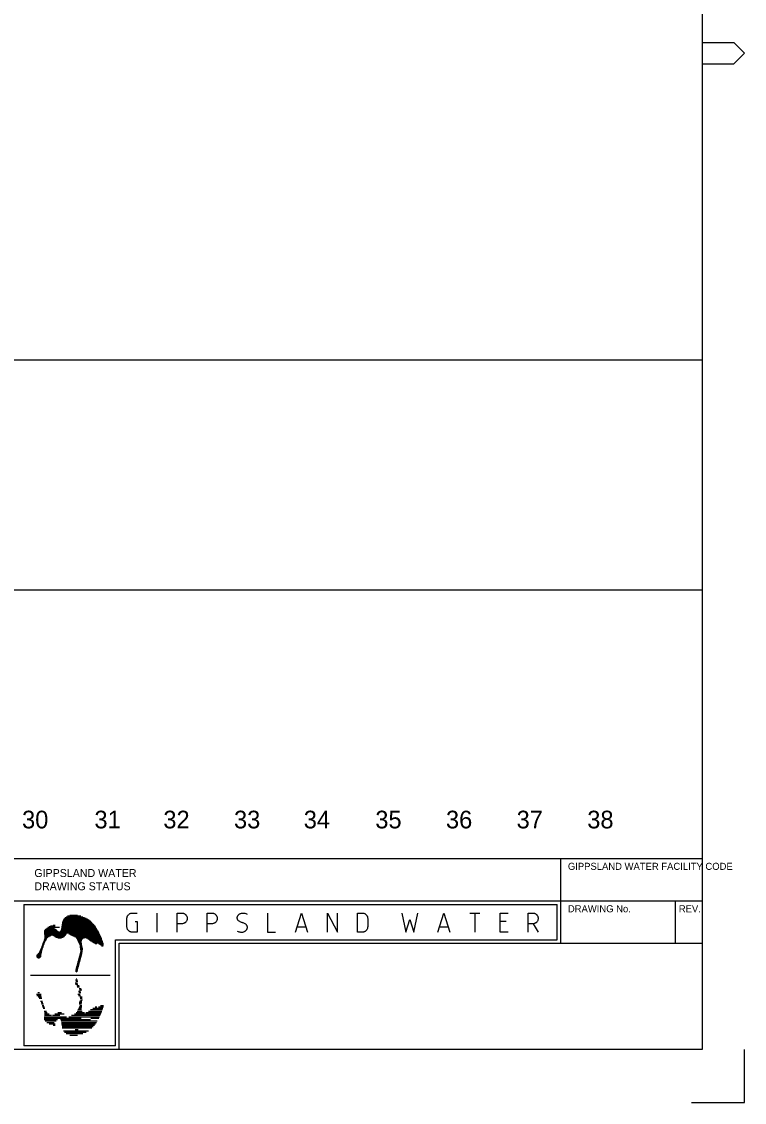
# Model space of a CAD drawing. Extents: x 0 to 841, y 0 to 594.
# Drawn here: x 636.4 to 841, y 0 to 305.7 of the extents above; entities that cross this region are included whole.
import ezdxf

# ---------------------------------------------------------------- set-up
doc = ezdxf.new("R2010")
doc.units = 0
doc.layers.add('A1BORDER', color=7, linetype='Continuous')
doc.layers.add('Level 1', color=7, linetype='Continuous')

msp = doc.modelspace()

# ---------------------------------------------------------------- linework, layer by layer
at = {"layer": 'A1BORDER'}
for p, q in [((829, 581), (829, 15)), ((829, 299.76), (838, 299.76)), ((838, 299.76), (841, 296.76)), ((838, 293.76), (841, 296.76)), ((829, 293.76), (838, 293.76)), ((592.5, 69), (829, 69)), ((789, 45), (789, 69)), ((28, 57), (829, 57)), ((637, 56), (788, 56)), ((637, 56), (637, 16)), ((788, 46), (788, 56)), ((821.5, 45), (821.5, 57)), ((648.53, 52.12), (654.64, 52.12)), ((648.74, 52.32), (654.24, 52.32)), ((649.02, 52.52), (653.76, 52.52)), ((649.39, 52.72), (653.15, 52.72)), ((650.01, 52.92), (652.2, 52.92)), ((643.04, 48.92), (646.16, 48.92)), ((643.26, 49.12), (645.9, 49.12)), ((643.54, 49.32), (645.57, 49.32)), ((643.85, 49.52), (647.09, 49.52)), ((644.18, 49.72), (645.89, 49.72)), ((644.54, 49.92), (645.36, 49.92)), ((645.37, 50.12), (645.86, 50.12)), ((647.61, 48.92), (657.8, 48.92)), ((647.63, 49.12), (657.68, 49.12)), ((647.66, 49.32), (657.57, 49.32)), ((647.69, 49.52), (657.44, 49.52)), ((647.71, 49.72), (657.31, 49.72)), ((647.75, 49.92), (657.17, 49.92)), ((647.78, 50.12), (657.02, 50.12)), ((647.81, 50.32), (656.86, 50.32)), ((647.85, 50.52), (656.69, 50.52)), ((647.88, 50.72), (656.5, 50.72)), ((647.91, 50.92), (656.3, 50.92)), ((647.96, 51.12), (656.08, 51.12)), ((648.03, 51.32), (655.85, 51.32)), ((648.12, 51.52), (655.59, 51.52)), ((648.23, 51.72), (655.31, 51.72)), ((648.37, 51.92), (655, 51.92)), ((642.72, 45.92), (643.3, 45.92)), ((642.73, 48.12), (658.25, 48.12)), ((642.74, 47.92), (658.35, 47.92)), ((642.75, 48.32), (646.79, 48.32)), ((642.79, 47.72), (649.08, 47.72)), ((642.79, 46.12), (643.4, 46.12)), ((642.81, 48.52), (646.55, 48.52)), ((642.83, 47.52), (648.95, 47.52)), ((642.84, 46.32), (643.5, 46.32)), ((642.85, 47.31), (644.88, 47.31)), ((642.87, 47.12), (644.57, 47.12)), ((642.87, 46.52), (643.6, 46.52)), ((642.88, 46.92), (644.23, 46.92)), ((642.88, 46.72), (643.83, 46.72)), ((642.9, 48.72), (646.37, 48.72)), ((645.14, 47.31), (648.83, 47.31)), ((645.49, 47.12), (648.67, 47.12)), ((645.76, 46.92), (648.42, 46.92)), ((646.05, 46.72), (648.11, 46.72)), ((646.62, 46.52), (647.67, 46.52)), ((647.19, 48.32), (658.14, 48.32)), ((647.42, 48.52), (658.03, 48.52)), ((647.54, 48.72), (657.92, 48.72)), ((649.72, 47.72), (658.45, 47.72)), ((650.12, 47.52), (658.55, 47.52)), ((650.48, 47.31), (658.64, 47.31)), ((650.87, 47.12), (658.73, 47.12)), ((651.36, 46.92), (658.82, 46.92)), ((651.76, 46.72), (658.9, 46.72)), ((651.88, 46.52), (654.15, 46.52)), ((651.99, 46.32), (653.71, 46.32)), ((652.1, 46.12), (653.52, 46.12)), ((652.2, 45.92), (653.4, 45.92)), ((654.57, 46.52), (658.99, 46.52)), ((655, 46.32), (659.07, 46.32)), ((655.31, 46.12), (659.14, 46.12)), ((655.62, 45.92), (659.22, 45.92)), ((663, 46), (788, 46)), ((663, 16), (663, 46)), ((641.55, 42.92), (642.2, 42.92)), ((641.64, 43.12), (642.25, 43.12)), ((641.73, 43.32), (642.3, 43.32)), ((641.82, 43.51), (642.35, 43.51)), ((641.91, 43.72), (642.41, 43.72)), ((641.99, 43.92), (642.48, 43.92)), ((642.06, 44.12), (642.55, 44.12)), ((642.13, 44.32), (642.62, 44.32)), ((642.21, 44.52), (642.69, 44.52)), ((642.28, 44.72), (642.76, 44.72)), ((642.35, 44.92), (642.83, 44.92)), ((642.43, 45.12), (642.9, 45.12)), ((642.5, 45.32), (643, 45.32)), ((642.57, 45.52), (643.1, 45.52)), ((642.65, 45.72), (643.2, 45.72)), ((652.31, 45.72), (653.33, 45.72)), ((652.41, 45.52), (653.31, 45.52)), ((652.5, 45.32), (653.34, 45.32)), ((652.6, 45.12), (653.38, 45.12)), ((652.69, 44.92), (653.41, 44.92)), ((652.78, 44.72), (653.44, 44.72)), ((652.83, 44.52), (653.48, 44.52)), ((652.86, 44.32), (653.53, 44.32)), ((652.89, 44.12), (653.57, 44.12)), ((652.91, 43.92), (653.62, 43.92)), ((652.94, 43.72), (653.67, 43.72)), ((652.97, 43.51), (653.71, 43.51)), ((653, 43.32), (653.69, 43.32)), ((653.02, 43.12), (653.67, 43.12)), ((653.05, 42.92), (653.64, 42.92)), ((655.93, 45.72), (659.29, 45.72)), ((656.24, 45.52), (659.35, 45.52)), ((656.55, 45.32), (659.42, 45.32)), ((656.86, 45.12), (657.74, 45.12)), ((657.17, 44.92), (657.68, 44.92)), ((657.51, 44.72), (657.54, 44.72)), ((657.91, 45.12), (659.48, 45.12)), ((658.19, 44.92), (659.54, 44.92)), ((658.47, 44.72), (659.59, 44.72)), ((658.75, 44.52), (659.58, 44.52)), ((659.02, 44.32), (659.47, 44.32)), ((664, 45), (829, 45)), ((664, 15), (664, 45)), ((640.62, 41.32), (641.88, 41.32)), ((640.63, 41.52), (641.93, 41.52)), ((640.72, 41.12), (641.73, 41.12)), ((640.73, 41.72), (641.95, 41.72)), ((640.9, 41.92), (641.97, 41.92)), ((641.03, 40.92), (641.43, 40.92)), ((641.1, 42.12), (642, 42.12)), ((641.25, 42.31), (642.04, 42.31)), ((641.37, 42.52), (642.09, 42.52)), ((641.46, 42.72), (642.15, 42.72)), ((652.3, 39.92), (652.93, 39.92)), ((652.36, 40.12), (652.99, 40.12)), ((652.41, 40.32), (653.04, 40.32)), ((652.47, 40.52), (653.1, 40.52)), ((652.52, 40.72), (653.15, 40.72)), ((652.57, 40.92), (653.2, 40.92)), ((652.63, 41.12), (653.26, 41.12)), ((652.68, 41.32), (653.31, 41.32)), ((652.74, 41.52), (653.37, 41.52)), ((652.79, 41.72), (653.41, 41.72)), ((652.85, 41.92), (653.45, 41.92)), ((652.9, 42.12), (653.49, 42.12)), ((652.95, 42.31), (653.53, 42.31)), ((652.99, 42.52), (653.57, 42.52)), ((653.03, 42.72), (653.61, 42.72)), ((651.63, 37.32), (652.23, 37.32)), ((651.64, 37.12), (652.17, 37.12)), ((651.65, 37.52), (652.28, 37.52)), ((651.71, 37.72), (652.34, 37.72)), ((651.76, 37.92), (652.39, 37.92)), ((651.79, 36.92), (651.9, 36.92)), ((651.82, 38.12), (652.44, 38.12)), ((651.87, 38.32), (652.5, 38.32)), ((651.92, 38.52), (652.55, 38.52)), ((651.98, 38.72), (652.61, 38.72)), ((652.03, 38.92), (652.66, 38.92)), ((652.09, 39.12), (652.72, 39.12)), ((652.14, 39.32), (652.77, 39.32)), ((652.2, 39.52), (652.82, 39.52)), ((652.25, 39.72), (652.88, 39.72)), ((638.93, 35.98), (661.47, 35.98)), ((651.54, 33.84), (652.17, 33.84)), ((651.63, 34.64), (652.23, 34.64)), ((651.71, 34.24), (652.34, 34.24)), ((651.79, 35.04), (651.9, 35.04)), ((640.62, 30.64), (641.88, 30.64)), ((641.03, 31.04), (641.43, 31.04)), ((651.65, 33.44), (652.28, 33.44)), ((652.03, 33.04), (652.66, 33.04)), ((652.14, 32.64), (652.77, 32.64)), ((652.34, 30.64), (652.97, 30.64)), ((652.47, 31.44), (653.1, 31.44)), ((652.57, 31.04), (653.2, 31.04)), ((652.66, 32.24), (653.29, 32.24)), ((652.77, 31.84), (653.4, 31.84)), ((640.73, 30.24), (641.95, 30.24)), ((641.1, 29.84), (642, 29.84)), ((641.37, 29.44), (642.09, 29.44)), ((641.73, 28.64), (642.3, 28.64)), ((641.91, 28.24), (642.41, 28.24)), ((642.06, 27.84), (642.55, 27.84)), ((652.45, 30.24), (653.07, 30.24)), ((652.66, 27.84), (653.35, 27.84)), ((652.72, 28.24), (653.44, 28.24)), ((652.77, 28.64), (653.46, 28.64)), ((652.9, 29.84), (653.49, 29.84)), ((652.99, 29.44), (653.57, 29.44)), ((653.05, 29.04), (653.64, 29.04)), ((642.21, 27.44), (642.69, 27.44)), ((642.35, 27.04), (642.83, 27.04)), ((642.5, 26.64), (643, 26.64)), ((642.79, 25.84), (643.4, 25.84)), ((642.85, 24.65), (644.88, 24.65)), ((642.87, 25.44), (643.6, 25.44)), ((642.88, 25.04), (644.23, 25.04)), ((645.14, 24.65), (647.18, 24.65)), ((645.76, 25.04), (648.42, 25.04)), ((646.62, 25.44), (647.67, 25.44)), ((650.48, 24.65), (658.64, 24.65)), ((651.36, 25.04), (658.82, 25.04)), ((651.88, 25.44), (654.15, 25.44)), ((652.1, 25.84), (653.52, 25.84)), ((652.31, 26.24), (653.33, 26.24)), ((652.5, 26.64), (653.34, 26.64)), ((652.69, 27.04), (653.41, 27.04)), ((652.83, 27.44), (653.48, 27.44)), ((654.57, 25.44), (658.99, 25.44)), ((655.31, 25.84), (659.14, 25.84)), ((655.93, 26.24), (659.29, 26.24)), ((656.55, 26.64), (659.42, 26.64)), ((657.17, 27.04), (657.68, 27.04)), ((658.19, 27.04), (659.54, 27.04)), ((658.75, 27.44), (659.58, 27.44)), ((642.73, 23.84), (653.27, 23.84)), ((642.79, 24.24), (649.08, 24.24)), ((642.81, 23.44), (646.55, 23.44)), ((643.04, 23.04), (646.16, 23.04)), ((643.54, 22.64), (645.57, 22.64)), ((644.18, 22.24), (645.89, 22.24)), ((645.37, 21.84), (645.86, 21.84)), ((647.42, 23.44), (655.89, 23.44)), ((647.61, 23.04), (657.8, 23.04)), ((647.66, 22.64), (657.57, 22.64)), ((647.71, 22.24), (657.31, 22.24)), ((647.78, 21.84), (657.02, 21.84)), ((647.85, 21.44), (656.69, 21.44)), ((649.72, 24.24), (658.45, 24.24)), ((655.94, 23.84), (658.25, 23.84)), ((647.91, 21.04), (656.3, 21.04)), ((648.23, 20.24), (655.31, 20.24)), ((648.53, 19.84), (654.64, 19.84)), ((649.02, 19.44), (653.76, 19.44)), ((650.01, 19.04), (652.2, 19.04)), ((651.57, 20.64), (652.44, 20.64)), ((663, 16), (637, 16)), ((829, 15), (28, 15)), ((829, 15), (829, 15)), ((841, 0), (841, 15)), ((826, 0), (841, 0))]:
    msp.add_line(p, q, dxfattribs=at)
for points in [[(668.49, 51.15), (669.06, 51.15), (669.06, 48.16), (667.64, 48.16), (667.51, 48.16), (667.39, 48.18), (667.28, 48.21), (667.15, 48.25), (667.04, 48.3), (666.93, 48.36), (666.82, 48.43), (666.73, 48.51), (666.64, 48.6), (666.55, 48.7), (666.48, 48.8), (666.41, 48.91), (666.35, 49.02), (666.31, 49.14), (666.27, 49.27), (666.24, 49.39), (666.22, 49.52), (666.22, 49.66), (666.22, 52.05), (666.22, 52.18), (666.24, 52.31), (666.27, 52.43), (666.31, 52.56), (666.35, 52.67), (666.41, 52.79), (666.48, 52.9), (666.55, 53), (666.64, 53.1), (666.73, 53.19), (666.82, 53.27), (666.93, 53.34), (667.04, 53.4), (667.15, 53.45), (667.28, 53.49), (667.39, 53.52), (667.51, 53.54), (667.64, 53.54), (669.06, 53.54)], [(674.74, 48.16), (674.74, 53.54)], [(680.42, 48.16), (680.42, 53.54), (681.84, 53.54), (681.96, 53.54), (682.08, 53.52), (682.2, 53.49), (682.32, 53.45), (682.43, 53.4), (682.54, 53.34), (682.65, 53.27), (682.74, 53.19), (682.84, 53.1), (682.92, 53), (682.99, 52.9), (683.06, 52.79), (683.12, 52.67), (683.17, 52.56), (683.21, 52.43), (683.23, 52.31), (683.25, 52.18), (683.26, 52.05), (683.25, 51.91), (683.23, 51.78), (683.21, 51.66), (683.17, 51.53), (683.12, 51.42), (683.06, 51.3), (682.99, 51.19), (682.92, 51.09), (682.84, 50.99), (682.74, 50.9), (682.65, 50.82), (682.54, 50.75), (682.43, 50.69), (682.32, 50.64), (682.2, 50.6), (682.08, 50.57), (681.96, 50.55), (681.84, 50.55), (680.42, 50.55)], [(688.93, 48.16), (688.93, 53.54), (690.35, 53.54), (690.47, 53.54), (690.59, 53.52), (690.71, 53.49), (690.83, 53.45), (690.94, 53.4), (691.05, 53.34), (691.16, 53.27), (691.26, 53.19), (691.35, 53.1), (691.43, 53), (691.51, 52.9), (691.57, 52.79), (691.63, 52.67), (691.68, 52.56), (691.72, 52.43), (691.75, 52.31), (691.76, 52.18), (691.77, 52.05), (691.76, 51.91), (691.75, 51.78), (691.72, 51.66), (691.68, 51.53), (691.63, 51.42), (691.57, 51.3), (691.51, 51.19), (691.43, 51.09), (691.35, 50.99), (691.26, 50.9), (691.16, 50.82), (691.05, 50.75), (690.94, 50.69), (690.83, 50.64), (690.71, 50.6), (690.59, 50.57), (690.47, 50.55), (690.35, 50.55), (688.93, 50.55)], [(697.45, 48.46), (697.67, 48.36), (697.9, 48.27), (698.12, 48.21), (698.36, 48.17), (698.6, 48.16), (698.84, 48.16), (698.87, 48.16), (699.03, 48.18), (699.18, 48.21), (699.33, 48.26), (699.48, 48.32), (699.62, 48.4), (699.72, 48.46), (699.81, 48.53), (699.9, 48.61), (699.98, 48.69), (700.05, 48.78), (700.11, 48.88), (700.17, 48.99), (700.22, 49.09), (700.25, 49.21), (700.28, 49.32), (700.29, 49.36), (700.3, 49.44), (700.3, 49.52), (700.3, 49.61), (700.29, 49.69), (700.27, 49.77), (700.25, 49.86), (700.22, 49.93), (700.18, 50.01), (700.14, 50.09), (700.09, 50.15), (700.04, 50.21), (700.01, 50.25), (699.85, 50.39), (699.69, 50.51), (699.52, 50.61), (699.34, 50.7), (699.15, 50.78), (698.95, 50.83), (698.87, 50.85), (698.68, 50.9), (698.49, 50.96), (698.3, 51.04), (698.12, 51.14), (697.96, 51.26), (697.8, 51.39), (697.73, 51.45), (697.67, 51.51), (697.62, 51.57), (697.58, 51.64), (697.53, 51.71), (697.5, 51.79), (697.47, 51.87), (697.46, 51.95), (697.44, 52.04), (697.43, 52.12), (697.43, 52.21), (697.44, 52.29), (697.45, 52.35), (697.47, 52.46), (697.51, 52.58), (697.55, 52.69), (697.61, 52.79), (697.67, 52.89), (697.74, 52.99), (697.82, 53.07), (697.9, 53.15), (697.99, 53.23), (698.02, 53.24), (698.15, 53.33), (698.3, 53.4), (698.44, 53.45), (698.6, 53.5), (698.75, 53.52), (698.87, 53.54), (699.11, 53.55), (699.35, 53.53), (699.58, 53.49), (699.82, 53.43), (700.04, 53.35), (700.27, 53.25)], [(705.96, 53.54), (705.96, 48.16), (708.23, 48.16)], [(713.91, 48.16), (715.61, 53.54), (717.32, 48.16)], [(722.99, 48.16), (722.99, 53.54), (725.83, 48.16), (725.83, 53.54)], [(731.52, 48.16), (731.52, 53.54), (732.94, 53.54), (733.06, 53.54), (733.18, 53.52), (733.3, 53.49), (733.42, 53.45), (733.53, 53.4), (733.64, 53.34), (733.75, 53.27), (733.84, 53.19), (733.94, 53.1), (734.02, 53), (734.09, 52.9), (734.16, 52.79), (734.22, 52.67), (734.27, 52.56), (734.31, 52.43), (734.33, 52.31), (734.35, 52.18), (734.36, 52.05), (734.36, 49.66), (734.35, 49.52), (734.33, 49.39), (734.31, 49.27), (734.27, 49.14), (734.22, 49.02), (734.16, 48.91), (734.09, 48.8), (734.02, 48.7), (733.94, 48.6), (733.84, 48.51), (733.75, 48.43), (733.64, 48.36), (733.53, 48.3), (733.42, 48.25), (733.3, 48.21), (733.18, 48.18), (733.06, 48.16), (732.94, 48.16), (731.52, 48.16)], [(744.01, 53.54), (745.14, 48.16), (746.28, 51.75), (747.41, 48.16), (748.55, 53.54)], [(754.22, 48.16), (755.92, 53.54), (757.63, 48.16)], [(763.31, 53.54), (766.15, 53.54)], [(764.73, 53.54), (764.73, 48.16)], [(774.09, 48.16), (771.82, 48.16), (771.82, 53.54), (774.09, 53.54)], [(779.78, 48.16), (779.78, 53.54), (781.2, 53.54), (781.32, 53.54), (781.44, 53.52), (781.56, 53.49), (781.68, 53.45), (781.79, 53.4), (781.9, 53.34), (782.01, 53.27), (782.1, 53.19), (782.2, 53.1), (782.28, 53), (782.35, 52.9), (782.42, 52.79), (782.48, 52.67), (782.53, 52.56), (782.56, 52.43), (782.59, 52.31), (782.61, 52.18), (782.61, 52.05), (782.61, 51.91), (782.59, 51.78), (782.56, 51.66), (782.53, 51.53), (782.48, 51.42), (782.42, 51.3), (782.35, 51.19), (782.28, 51.09), (782.2, 50.99), (782.1, 50.9), (782.01, 50.82), (781.9, 50.75), (781.79, 50.69), (781.68, 50.64), (781.56, 50.6), (781.44, 50.57), (781.32, 50.55), (781.2, 50.55), (779.78, 50.55)], [(714.48, 49.66), (716.75, 49.66)], [(754.79, 49.66), (757.06, 49.66)], [(773.53, 51.15), (771.82, 51.15)], [(781.2, 50.55), (782.61, 48.16)]]:
    msp.add_lwpolyline(points, dxfattribs=at)
at = {"layer": 'Level 1'}
for p, q in [((28, 210), (829, 210)), ((28, 145), (829, 145))]:
    msp.add_line(p, q, dxfattribs=at)

# ---------------------------------------------------------------- texts
at = {"layer": 'A1BORDER'}
for s, height, p in [('GIPPSLAND WATER FACILITY CODE', 2, (791.03, 65.77)), ('GIPPSLAND WATER', 2.25, (640, 63.75)), ('DRAWING STATUS', 2.25, (640, 60)), ('DRAWING No.', 2, (791.03, 53.77)), ('REV.', 2, (822.43, 53.77))]:
    msp.add_text(s, height=height, dxfattribs=at).set_placement(p)
at = {"layer": 'Level 1'}
for s, p in [('30', (636.52, 77.5)), ('31', (657.01, 77.5)), ('32', (676.52, 77.5)), ('33', (696.52, 77.5)), ('34', (716.26, 77.5)), ('35', (736.52, 77.5)), ('36', (756.52, 77.5)), ('37', (776.52, 77.5)), ('38', (796.52, 77.5))]:
    msp.add_text(s, height=5, dxfattribs=at).set_placement(p)

doc.saveas('drawing.dxf')
